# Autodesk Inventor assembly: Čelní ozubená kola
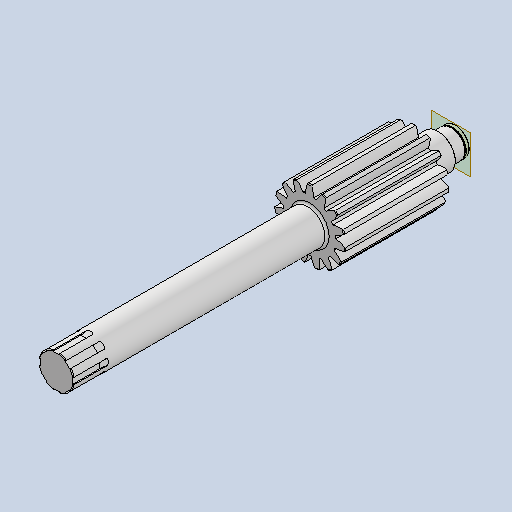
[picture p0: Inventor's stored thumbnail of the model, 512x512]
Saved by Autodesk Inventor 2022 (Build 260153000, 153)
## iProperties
ClientObjectVersion: 1
Created: 2025-05
Part Number: Čelní ozubená kola
Document SubType Name: Assembly
Designer: jbart
Categories: <?xml version="1.0" encoding="UTF-16"?> <MemberInstance><Categories><FamilyTemplate/><ParamToTemplateMap><ParamToTemplate><ParamToTemplate CategoryParameter="//
Author: jbart
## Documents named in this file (2)
- C:\Users\jbart\OneDrive\Dokumenty\Inventor\Převodovka navijáku\Hřídel II\Design Accelerator\Čelní ozubená kola1.iam
- C:\Users\jbart\OneDrive\Dokumenty\Inventor\Převodovka navijáku\Hřídel II\Design Accelerator\Čelní ozubené kolo11.ipt
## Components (1 placed, 1 different names)
1. Čelní ozubené kolo1:1
